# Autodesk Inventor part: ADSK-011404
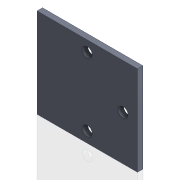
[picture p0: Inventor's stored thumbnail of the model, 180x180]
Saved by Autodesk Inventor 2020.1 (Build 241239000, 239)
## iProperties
Created: 2000-01
Part Number: ADSK-011404
Material: Pearson Stainless Steel
Document SubType Name: Modeling
Designer: glanglot
Density: 8.03 g/cm^3
Appearance: Pearson-Stainless
Mass: 64.5305 g
Surface Area: 61.4296 cm^2
Volume: 8.03618 cm^3
Control State: 0
Master: False
Checked Out: False
Shininess: 57.0
Length Units: 11269
Angle Units: 11279
Time Units: 11290
Mass Units: 11283
Length Display Precision: 5
Angle Display Precision: 5
Compacted: True
CUTLENGTH: 2.25
MATERIAL DESC: FLAT,S/S,0.13 X 2.00
MATERIAL_NUMBER: A088298
Dimensions: 55x50x3 mm
Mass: 0,065 kg
Density: 8.03
Volumn: 9.048045760202035
Area: 65.27550362453616
PropertySet Name: Model Information
Author: glanglot
Revision Number: -
Title: ADSK-011404
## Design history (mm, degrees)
node "Solide1"
  node "Extrusion2" dims "d17" = 3, "d18" = 0
  node "Hole1" dims "d19" = 5.5, "d20" = 9.525, "d21" = 6.35, "d22" = 60 deg, "d23" = 19.05, "d24" = 118 deg, "d25" = 6
sketch "Sketch1"
  geometry: L1 (-27.5, -25)-(-27.5, 25); L2 (27.5, 25)-(-27.5, 25); L3 (27.5, -25)-(27.5, 25); L4 (-27.5, -25)-(27.5, -25); L5 (0, 25)-(0, -25); L6 (27.5, 0)-(-27.5, 0); L7 (-27.5, -25)-(-27.5, 25); 4 further points
  constraints: 14 end point, 6 midpoint, 3 point on line, 2 perpendicular, 1 horizontal
  dimensions: "d0" = 50 distance between parallel lines of L4 L2; "d9" = 19 distance from line of L6 point (0, 19); "d10" = 19 distance from line of point (0, -19) L6 (= d9); "d12" = 20 distance from line of point (20, 0) L5; "d26" = 55 distance of L1.start L3.start
node "Corps solides"
node "Corps surfaciques"
